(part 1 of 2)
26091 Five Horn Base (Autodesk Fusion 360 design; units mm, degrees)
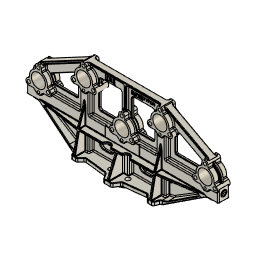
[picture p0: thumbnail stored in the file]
parameter "Bolt_Hole_Tolerance" = 0.7937 (= "( 1 / 32 ) * 1 in")
parameter "Bell_Tolerance" = 0.1984 (= "( 1 / 128 ) * 1 in")
parameter "Dowel_Hole_Tolerance" = 0.0992 (= "( 1 / 256 ) * 1 in")
sketch "Layout Profile" plane through (0, 0, 0) normal (0, 1, 0) x axis (1, 0, 0)
  line L1 (50.8, 0) -> (-50.8, 0)
  line L2 (0, -212.725) -> (0, 0)
  line L3 (263.525, -136.525) -> (-263.525, -136.525)
  line L4 (120.65, -212.725) -> (-120.65, -212.725)
  line L5 (57.5017, -12.7) -> (-57.5017, -12.7)
  circle C1 centre (120.65, -212.725) radius 80.9625
  circle C2 centre (-120.65, -212.725) radius 69.0562
  circle C3 centre (-263.525, -136.525) radius 101.6
  circle C4 centre (263.525, -136.525) radius 114.3
  arc A1 centre (0, -136.525) radius 136.525 clockwise from (57.5017, -12.7) to (-57.5017, -12.7)
  point P3 (0, 0)
  point P8 (0, -136.525)
  point P11 (0, -212.725)
  point P5 (0, -212.725)
  point P10 (120.65, -212.725)
  point P12 (120.65, -212.725)
  point P9 (-120.65, -212.725)
  point P13 (-120.65, -212.725)
  point P6 (-263.525, -136.525)
  point P14 (-263.525, -136.525)
  point P15 (0, -136.525)
  point P7 (263.525, -136.525)
  point P16 (263.525, -136.525)
  point P4 (0, 0)
  point P1 (-50.8, 0)
  point P2 (50.8, 0)
  horizontal L1
  midpoint L1 P3
  perpendicular L1 L2
  horizontal L3
  midpoint L3 P8
  coincident L2 P8
  horizontal L4
  midpoint L4 P11
  coincident P5 P11
  coincident P10 P12
  coincident P9 P13
  coincident P6 P14
  coincident P8 P15
  coincident P7 P16
  perpendicular L2 L5
  coincident L1 P4
  coincident P3 P4
  dimension "d1" distance P1 P2 = 101.6
  dimension "d2" distance L2 P6 = 263.525 (= "10 3/8")
  dimension "d3" distance L1 L3 = 136.525 (= "5 3/8")
  dimension "d4" distance P9 P10 = 241.3 (= "9 1/2")
  dimension "d5" distance L3 L4 = 76.2
  dimension "d6" diameter C1 = 161.925 (= "6 3/8")
  dimension "d7" diameter C2 = 138.1125 (= "5 7/16")
  dimension "d8" diameter C3 = 203.2
  dimension "d9" diameter A1 = 273.05 (= "10 3/4")
  dimension "d10" diameter C4 = 228.6
  dimension "d11" distance L1 L5 = 12.7 (= "( 1 / 2 ) * 1 in")
sketch "Main Profile" plane through (0, 0, 0) normal (0, 1, 0) x axis (1, 0, 0)
  line L1 (0, -171.45) -> (0, -136.525)
  line L2 (30.2459, -119.0625) -> (0, -136.525)
  line L3 (-30.2459, -119.0625) -> (0, -136.525)
  line L4 (0, -180.975) -> (0, -171.45)
  line L5 (3.175, -180.975) -> (-3.175, -180.975)
  line L6 (9.525, -165.6244) -> (9.525, -174.625)
  line L7 (35.0084, -127.3114) -> (29.9633, -130.2242)
  line L8 (30.2459, -109.5375) -> (15.0813, -109.5375)
  line L9 (0, -104.775) -> (0, -136.525)
  line L10 (0, -98.425) -> (0, -104.775)
  line L11 (3.9688, -98.425) -> (-3.9687, -98.425)
  line L12 (15.0813, -109.5375) -> (3.9688, -98.425)
  line L13 (-15.0812, -109.5375) -> (-3.9687, -98.425)
  line L14 (-30.2459, -109.5375) -> (-15.0812, -109.5375)
  line L15 (-35.0084, -127.3114) -> (-29.9633, -130.2242)
  line L16 (-9.525, -165.6244) -> (-9.525, -174.625)
  line L17 (120.65, -247.65) -> (120.65, -212.725)
  line L18 (150.8959, -195.2625) -> (120.65, -212.725)
  line L19 (90.4041, -195.2625) -> (120.65, -212.725)
  line L20 (120.65, -257.175) -> (120.65, -247.65)
  line L21 (123.825, -257.175) -> (117.475, -257.175)
  line L22 (130.175, -241.8244) -> (130.175, -250.825)
  line L23 (155.6584, -203.5114) -> (150.6133, -206.4242)
  line L24 (150.8959, -185.7375) -> (135.7312, -185.7375)
  line L25 (120.65, -180.975) -> (120.65, -212.725)
  line L26 (120.65, -174.625) -> (120.65, -180.975)
  line L27 (124.6188, -174.625) -> (116.6813, -174.625)
  line L28 (135.7312, -185.7375) -> (124.6188, -174.625)
  line L29 (111.125, -241.8244) -> (111.125, -250.825)
  line L30 (85.6416, -203.5114) -> (90.6867, -206.4242)
  line L31 (90.4041, -185.7375) -> (105.5688, -185.7375)
  line L32 (105.5688, -185.7375) -> (116.6813, -174.625)
  line L33 (0, -136.525) -> (0, 0)
  line L34 (-90.4041, -195.2625) -> (-120.65, -212.725)
  line L35 (-120.65, -257.175) -> (-120.65, -247.65)
  line L36 (-124.6187, -174.625) -> (-116.6812, -174.625)
  line L37 (-85.6416, -203.5114) -> (-90.6867, -206.4242)
  line L38 (-120.65, -174.625) -> (-120.65, -180.975)
  line L39 (-150.8959, -195.2625) -> (-120.65, -212.725)
  line L40 (-120.65, -180.975) -> (-120.65, -212.725)
  line L41 (-130.175, -241.8244) -> (-130.175, -250.825)
  line L42 (-105.5688, -185.7375) -> (-116.6812, -174.625)
  line L43 (-135.7312, -185.7375) -> (-124.6187, -174.625)
  line L44 (-120.65, -247.65) -> (-120.65, -212.725)
  line L45 (-111.125, -241.8244) -> (-111.125, -250.825)
  line L46 (-150.8959, -185.7375) -> (-135.7312, -185.7375)
  line L47 (-155.6584, -203.5114) -> (-150.6133, -206.4242)
  line L48 (-123.825, -257.175) -> (-117.475, -257.175)
  line L49 (-90.4041, -185.7375) -> (-105.5688, -185.7375)
  line L50 (263.525, -171.45) -> (263.525, -136.525)
  line L51 (293.7709, -119.0625) -> (263.525, -136.525)
  line L52 (233.2791, -119.0625) -> (263.525, -136.525)
  line L53 (263.525, -180.975) -> (263.525, -171.45)
  line L54 (266.7, -180.975) -> (260.35, -180.975)
  line L55 (273.05, -165.6244) -> (273.05, -174.625)
  line L56 (298.5334, -127.3114) -> (293.4883, -130.2242)
  line L57 (293.7709, -109.5375) -> (278.6063, -109.5375)
  line L58 (263.525, -104.775) -> (263.525, -136.525)
  line L59 (263.525, -98.425) -> (263.525, -104.775)
  line L60 (267.4938, -98.425) -> (259.5563, -98.425)
  line L61 (278.6063, -109.5375) -> (267.4938, -98.425)
  line L62 (248.4438, -109.5375) -> (259.5563, -98.425)
  line L63 (228.5166, -127.3114) -> (233.5617, -130.2242)
  line L64 (254, -165.6244) -> (254, -174.625)
  line L65 (233.2791, -109.5375) -> (248.4438, -109.5375)
  line L66 (-233.2791, -119.0625) -> (-263.525, -136.525)
  line L67 (-293.7709, -109.5375) -> (-278.6063, -109.5375)
  line L68 (-228.5166, -127.3114) -> (-233.5617, -130.2242)
  line L69 (-248.4437, -109.5375) -> (-259.5562, -98.425)
  line L70 (-293.7709, -119.0625) -> (-263.525, -136.525)
  line L71 (-263.525, -104.775) -> (-263.525, -136.525)
  line L72 (-273.05, -165.6244) -> (-273.05, -174.625)
  line L73 (-266.7, -180.975) -> (-260.35, -180.975)
  line L74 (-254, -165.6244) -> (-254, -174.625)
  line L75 (-278.6063, -109.5375) -> (-267.4937, -98.425)
  line L76 (-267.4937, -98.425) -> (-259.5562, -98.425)
  line L77 (-298.5334, -127.3114) -> (-293.4883, -130.2242)
  line L78 (-263.525, -180.975) -> (-263.525, -171.45)
  line L79 (-233.2791, -109.5375) -> (-248.4437, -109.5375)
  line L80 (-263.525, -171.45) -> (-263.525, -136.525)
  line L81 (-263.525, -98.425) -> (-263.525, -104.775)
  line L82 (263.525, -136.525) -> (-263.525, -136.525)
  line L83 (120.65, -212.725) -> (-120.65, -212.725)
  line L84 (50.8, 0) -> (-50.8, 0)
  line L85 (148.2214, -15.875) -> (-148.2214, -15.875)
  line L86 (51.5938, -3.175) -> (50.8, 0)
  line L87 (139.7, -3.175) -> (51.5938, -3.175)
  line L88 (120.65, 0) -> (120.65, -212.725)
  line L89 (-120.65, 0) -> (-120.65, -212.725)
  line L90 (263.525, 0) -> (50.8, 0)
  line L91 (263.525, -136.525) -> (263.525, 0)
  line L92 (-263.525, 0) -> (-50.8, 0)
  line L93 (-263.525, -136.525) -> (-263.525, 0)
  line L94 (0, -212.725) -> (0, -136.525)
  line L95 (269.6882, -180.2279) -> (126.8132, -256.4279)
  line L96 (256.8125, -179.8984) -> (130.175, -247.4383)
  line L97 (237.8236, -161.2391) -> (169.4422, -197.7091)
  line L98 (303.2959, -79.375) -> (303.2959, -119.0625)
  line L99 (3.175, -79.375) -> (303.2959, -79.375)
  line L100 (223.8873, -117.475) -> (134.9375, -117.475)
  line L101 (157.1625, -136.525) -> (228.7446, -136.525)
  line L102 (123.825, -15.875) -> (123.825, -174.625)
  line L103 (117.475, -15.875) -> (117.475, -174.625)
  line L104 (263.525, -79.375) -> (139.7, -3.175)
  line L105 (251.4089, -79.375) -> (148.2214, -15.875)
  line L106 (263.525, -85.725) -> (263.525, -79.375)
  line L107 (3.175, -85.725) -> (263.525, -85.725)
  line L108 (3.175, -98.425) -> (3.175, -85.725)
  line L109 (3.175, -15.875) -> (3.175, -79.375)
  line L110 (3.175, -79.375) -> (3.175, -85.725)
  line L111 (134.9375, -79.375) -> (134.9375, -184.9438)
  line L112 (106.3625, -79.375) -> (106.3625, -184.9438)
  line L113 (134.9375, -15.875) -> (134.9375, -79.375)
  line L114 (106.3625, -15.875) -> (106.3625, -79.375)
  line L115 (153.9875, -182.5003) -> (153.9875, -139.7)
  line L116 (-117.475, -257.175) -> (117.475, -257.175)
  line L117 (0, -257.175) -> (0, -212.725)
  line L118 (3.175, -250.825) -> (111.125, -250.825)
  line L119 (3.175, -180.975) -> (3.175, -250.825)
  line L120 (80.9625, -225.425) -> (22.225, -225.425)
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  point P4 (0, -136.525)
  point P7 (0, -136.525)
  point P8 (0, -136.525)
  point P9 (0, -171.45)
  point P10 (0, -171.45)
  point P17 (0, -171.45)
  point P21 (0, -180.975)
  point P18 (0, -180.975)
  point P35 (0, -136.525)
  point P36 (0, -104.775)
  point P37 (0, -104.775)
  point P38 (0, -104.775)
  point P42 (0, -98.425)
  point P39 (0, -98.425)
  point P20 (3.175, -180.975)
  point P57 (-3.175, -180.975)
  point P22 (9.525, -174.625)
  point P55 (-9.525, -174.625)
  point P24 (9.525, -165.6244)
  point P54 (-9.525, -165.6244)
  point P25 (11.43, -162.7144)
  point P52 (-11.43, -162.7144)
  point P27 (28.3957, -133.329)
  point P50 (-28.3957, -133.329)
  point P29 (29.9633, -130.2242)
  point P48 (-29.9633, -130.2242)
  point P31 (35.0084, -127.3114)
  point P47 (-35.0084, -127.3114)
  point P32 (15.0813, -109.5375)
  point P44 (-15.0812, -109.5375)
  point P33 (30.2459, -109.5375)
  point P45 (-30.2459, -109.5375)
  point P41 (3.9688, -98.425)
  point P43 (-3.9687, -98.425)
  point P5 (120.65, -212.725)
  point P58 (120.65, -212.725)
  point P59 (120.65, -212.725)
  point P60 (120.65, -247.65)
  point P61 (120.65, -247.65)
  point P68 (120.65, -247.65)
  point P72 (120.65, -257.175)
  point P69 (120.65, -257.175)
  point P86 (120.65, -212.725)
  point P87 (120.65, -180.975)
  point P88 (120.65, -180.975)
  point P89 (120.65, -180.975)
  point P93 (120.65, -174.625)
  point P90 (120.65, -174.625)
  point P71 (123.825, -257.175)
  point P95 (117.475, -257.175)
  point P73 (130.175, -250.825)
  point P96 (111.125, -250.825)
  point P75 (130.175, -241.8244)
  point P97 (111.125, -241.8244)
  point P76 (132.08, -238.9144)
  point P99 (109.22, -238.9144)
  point P78 (149.0457, -209.529)
  point P101 (92.2543, -209.529)
  point P80 (150.6133, -206.4242)
  point P103 (90.6867, -206.4242)
  point P82 (155.6584, -203.5114)
  point P104 (85.6416, -203.5114)
  point P83 (135.7312, -185.7375)
  point P107 (105.5688, -185.7375)
  point P84 (150.8959, -185.7375)
  point P106 (90.4041, -185.7375)
  point P92 (124.6188, -174.625)
  point P108 (116.6813, -174.625)
  point P1 (0, 0)
  point P109 (0, 0)
  point P28 (0, -136.525)
  point P110 (0, -136.525)
  point P156 (-120.65, -212.725)
  point P151 (-120.65, -212.725)
  point P141 (-120.65, -247.65)
  point P63 (120.65, -212.725)
  point P147 (-120.65, -212.725)
  point P64 (150.8959, -195.2625)
  point P139 (-150.8959, -195.2625)
  point P66 (120.65, -212.725)
  point P137 (-120.65, -212.725)
  point P67 (90.4041, -195.2625)
  point P158 (-90.4041, -195.2625)
  point P144 (-120.65, -247.65)
  point P114 (-120.65, -257.175)
  point P70 (117.475, -257.175)
  point P140 (-117.475, -257.175)
  point P120 (-123.825, -257.175)
  point P123 (-120.65, -257.175)
  point P115 (-130.175, -250.825)
  point P118 (-130.175, -241.8244)
  point P138 (-132.08, -238.9144)
  point P155 (-149.0457, -209.529)
  point P159 (-150.6133, -206.4242)
  point P161 (-155.6584, -203.5114)
  point P136 (-135.7312, -185.7375)
  point P134 (-150.8959, -185.7375)
  point P112 (-120.65, -212.725)
  point P133 (-120.65, -180.975)
  point P111 (-120.65, -180.975)
  point P121 (-120.65, -174.625)
  point P91 (116.6813, -174.625)
  point P162 (-116.6812, -174.625)
  point P116 (-124.6187, -174.625)
  point P119 (-120.65, -174.625)
  point P153 (-117.475, -257.175)
  point P117 (-111.125, -250.825)
  point P150 (-111.125, -241.8244)
  point P145 (-109.22, -238.9144)
  point P152 (-92.2543, -209.529)
  point P129 (-90.6867, -206.4242)
  point P130 (-85.6416, -203.5114)
  point P146 (-90.4041, -185.7375)
  point P131 (-105.5688, -185.7375)
  point P124 (-116.6812, -174.625)
  point P6 (263.525, -136.525)
  point P163 (263.525, -136.525)
  point P164 (263.525, -136.525)
  point P165 (263.525, -171.45)
  point P166 (263.525, -171.45)
  point P173 (263.525, -171.45)
  point P177 (263.525, -180.975)
  point P174 (263.525, -180.975)
  point P191 (263.525, -104.775)
  point P192 (263.525, -104.775)
  point P193 (263.525, -104.775)
  point P197 (263.525, -98.425)
  point P194 (263.525, -98.425)
  point P176 (266.7, -180.975)
  point P212 (260.35, -180.975)
  point P178 (273.05, -174.625)
  point P210 (254, -174.625)
  point P180 (273.05, -165.6244)
  point P209 (254, -165.6244)
  point P181 (274.955, -162.7144)
  point P207 (252.095, -162.7144)
  point P183 (291.9207, -133.329)
  point P205 (235.1293, -133.329)
  point P185 (293.4883, -130.2242)
  point P203 (233.5617, -130.2242)
  point P187 (298.5334, -127.3114)
  point P201 (228.5166, -127.3114)
  point P188 (278.6063, -109.5375)
  point P199 (248.4438, -109.5375)
  point P189 (293.7709, -109.5375)
  point P202 (233.2791, -109.5375)
  point P196 (267.4938, -98.425)
  point P198 (259.5563, -98.425)
  point P213 (248.4438, -109.5375)
  point P214 (233.2791, -109.5375)
  point P236 (-263.525, -136.525)
  point P215 (-263.525, -136.525)
  point P217 (-263.525, -171.45)
  point P167 (263.525, -136.525)
  point P230 (-263.525, -136.525)
  point P168 (293.7709, -119.0625)
  point P229 (-293.7709, -119.0625)
  point P170 (263.525, -136.525)
  point P218 (-263.525, -136.525)
  point P171 (233.2791, -119.0625)
  point P223 (-233.2791, -119.0625)
  point P227 (-263.525, -171.45)
  point P262 (-263.525, -180.975)
  point P175 (260.35, -180.975)
  point P238 (-260.35, -180.975)
  point P264 (-266.7, -180.975)
  point P231 (-263.525, -180.975)
  point P254 (-273.05, -174.625)
  point P248 (-273.05, -165.6244)
  point P265 (-274.955, -162.7144)
  point P255 (-291.9207, -133.329)
  point P267 (-293.4883, -130.2242)
  point P260 (-298.5334, -127.3114)
  point P257 (-278.6063, -109.5375)
  point P266 (-293.7709, -109.5375)
  point P224 (-263.525, -104.775)
  point P226 (-263.525, -104.775)
  point P225 (-263.525, -98.425)
  point P195 (259.5563, -98.425)
  point P239 (-259.5562, -98.425)
  point P222 (-267.4937, -98.425)
  point P251 (-263.525, -98.425)
  point P244 (-259.5562, -98.425)
  point P234 (-248.4437, -109.5375)
  point P220 (-228.5166, -127.3114)
  point P250 (-233.2791, -109.5375)
  point P235 (-233.5617, -130.2242)
  point P233 (-235.1293, -133.329)
  point P232 (-252.095, -162.7144)
  point P219 (-254, -165.6244)
  point P216 (-254, -174.625)
  point P256 (-260.35, -180.975)
  point P249 (-248.4437, -109.5375)
  point P237 (-233.2791, -109.5375)
  point P268 (263.525, -136.525)
  point P3 (-120.65, -212.725)
  point P269 (-120.65, -212.725)
  point P272 (0, 0)
  point P275 (0, -15.875)
  point P278 (120.65, -212.725)
  point P206 (263.525, -136.525)
  point P282 (263.525, -136.525)
  point P279 (120.65, 0)
  point P263 (-263.525, -136.525)
  point P284 (-263.525, -136.525)
  point P280 (-120.65, 0)
  point P285 (0, -212.725)
  point P288 (130.175, -247.4383)
  point P301 (228.7446, -136.525)
  point P303 (157.1625, -136.525)
  point P308 (263.525, -79.375)
  point P309 (251.4089, -79.375)
  point P310 (263.525, -85.725)
  point P313 (3.175, -15.875)
  point P305 (123.825, -15.875)
  point P307 (117.475, -15.875)
  point P314 (134.9375, -184.9438)
  point P316 (106.3625, -184.9438)
  point P315 (134.9375, -79.375)
  point P317 (106.3625, -79.375)
  point P318 (134.9375, -15.875)
  point P319 (106.3625, -15.875)
  point P304 (123.825, -174.625)
  point P306 (117.475, -174.625)
  point P299 (134.9375, -117.475)
  point P312 (3.175, -98.425)
  point P327 (0, -257.175)
  point P330 (3.175, -180.975)
  point P344 (34.7804, -136.525)
  point P346 (80.9625, -136.525)
  point P352 (273.05, -172.446)
  point P357 (3.175, -247.65)
  point P356 (6.35, -250.825)
  point P271 (50.8, 0)
  point P373 (-50.8, 0)
  point P274 (148.2214, -15.875)
  point P377 (-148.2214, -15.875)
  point P276 (51.5938, -3.175)
  point P374 (-51.5937, -3.175)
  point P277 (139.7, -3.175)
  point P375 (-139.7, -3.175)
  point P290 (169.4422, -197.7091)
  point P386 (-169.4422, -197.7091)
  point P291 (237.8236, -161.2391)
  point P387 (-237.8236, -161.2391)
  point P292 (238.8018, -156.4455)
  point P389 (-238.8018, -156.4455)
  point P294 (231.9065, -139.4114)
  point P391 (-231.9065, -139.4114)
  point P296 (303.2959, -119.0625)
  point P379 (-303.2959, -119.0625)
  point P297 (303.2959, -79.375)
  point P361 (-303.2959, -79.375)
  point P298 (3.175, -79.375)
  point P362 (-3.175, -79.375)
  point P380 (-134.9375, -117.475)
  point P300 (223.8873, -117.475)
  point P382 (-223.8873, -117.475)
  point P393 (-228.7446, -136.525)
  point P398 (-157.1625, -136.525)
  point P363 (-123.825, -174.625)
  point P364 (-123.825, -15.875)
  point P365 (-117.475, -174.625)
  point P366 (-117.475, -15.875)
  point P376 (-263.525, -79.375)
  point P378 (-251.4089, -79.375)
  point P359 (-263.525, -85.725)
  point P311 (3.175, -85.725)
  point P360 (-3.175, -85.725)
  point P371 (-134.9375, -184.9438)
  point P369 (-134.9375, -79.375)
  point P372 (-106.3625, -184.9438)
  point P367 (-106.3625, -79.375)
  point P370 (-134.9375, -15.875)
  point P368 (-106.3625, -15.875)
  point P320 (153.9875, -139.7)
  point P396 (-153.9875, -139.7)
  point P322 (153.9875, -182.5003)
  point P395 (-153.9875, -182.5003)
  point P323 (156.5609, -187.6052)
  point P384 (-156.5609, -187.6052)
  point P325 (160.2308, -193.3687)
  point P383 (-160.2308, -193.3687)
  point P328 (111.125, -250.825)
  point P414 (-111.125, -250.825)
  point P329 (3.175, -250.825)
  point P415 (-3.175, -250.825)
  point P419 (-3.175, -180.975)
  point P331 (22.225, -225.425)
  point P409 (-22.225, -225.425)
  point P332 (80.9625, -225.425)
  point P410 (-80.9625, -225.425)
  point P333 (15.875, -219.075)
  point P407 (-15.875, -219.075)
  point P335 (15.875, -165.7971)
  point P406 (-15.875, -165.7971)
  point P337 (87.3125, -184.2162)
  point P411 (-87.3125, -184.2162)
  point P339 (87.3125, -142.875)
  point P413 (-87.3125, -142.875)
  point P340 (17.3182, -163.136)
  point P404 (-17.3182, -163.136)
  point P342 (31.6185, -139.4114)
  point P402 (-31.6185, -139.4114)
  point P399 (-34.7804, -136.525)
  point P400 (-80.9625, -136.525)
  point P348 (39.6377, -117.475)
  point P381 (-39.6377, -117.475)
  point P418 (-6.35, -250.825)
  point P417 (-3.175, -247.65)
  point P286 (126.8132, -256.4279)
  point P420 (-126.8132, -256.4279)
  point P287 (269.6882, -180.2279)
  point P421 (-269.6882, -180.2279)
  point P422 (-130.175, -247.4383)
  point P289 (256.8125, -179.8984)
  point P423 (-256.8125, -179.8984)
  point P424 (62.7063, -79.375)
  point P425 (62.7063, -15.875)
  point P426 (-3.175, -79.375)
  point P428 (-3.175, -85.725)
  point P429 (-3.175, -98.425)
  point P427 (-3.175, -15.875)
  point P431 (106.3625, -47.625)
  point P448 (-62.7063, -79.375)
  point P449 (-62.7063, -15.875)
  point P430 (19.05, -47.625)
  point P446 (-19.05, -47.625)
  point P447 (-106.3625, -47.625)
  point P432 (53.1813, -60.325)
  point P443 (-53.1813, -60.325)
  point P433 (72.2313, -60.325)
  point P441 (-72.2313, -60.325)
  point P434 (53.1813, -34.925)
  point P445 (-53.1813, -34.925)
  point P435 (72.2313, -34.925)
  point P442 (-72.2313, -34.925)
  point P450 (134.9375, -54.3904)
  point P454 (173.5531, -79.375)
  point P461 (-134.9375, -54.3904)
  point P451 (139.7765, -51.6864)
  point P459 (-139.7765, -51.6864)
  point P453 (175.2172, -73.496)
  point P458 (-175.2172, -73.496)
  point P457 (-173.5531, -79.375)
  point P462 (19.05, -79.375)
  point P463 (19.05, -15.875)
  point P465 (-19.05, -15.875)
  point P466 (0, 0)
  point P468 (0, -79.375)
  point P475 (-80.9625, -225.425)
  point P336 (85.7041, -186.9778)
  point P482 (-85.7041, -186.9778)
  point P480 (-87.3125, -184.2162)
  point P469 (87.3125, -219.075)
  point P476 (-87.3125, -219.075)
  point P471 (87.3125, -208.0247)
  point P477 (-87.3125, -208.0247)
  point P472 (84.7391, -202.9198)
  point P479 (-84.7391, -202.9198)
  point P12 (0, -136.525)
  point P40 (-3.9687, -98.425)
  point P15 (0, -136.525)
  point P184 (263.525, -136.525)
  point P270 (-50.8, 0)
  point P438 (40.4813, -47.625)
  point P439 (84.9313, -47.625)
  coincident P4 P7
  coincident P4 P8
  vertical L1
  coincident P9 P10
  coincident P10 P17
  vertical L4
  horizontal L5
  midpoint L5 P21
  coincident P18 P21
  vertical L6
  horizontal L8
  coincident P4 P35
  vertical L9
  coincident P36 P37
  coincident P37 P38
  parallel L9 L10
  horizontal L11
  midpoint L11 P42
  coincident P39 P42
  symmetric L1 P20 P57
  symmetric L1 P22 P55
  symmetric L1 P24 P54
  symmetric L1 P25 P52
  symmetric L1 P27 P50
  symmetric L1 P29 P48
  symmetric L1 P31 P47
  symmetric L1 P32 P44
  symmetric L1 P33 P45
  symmetric L1 P41 P43
  coincident P5 P58
  coincident P58 P59
  vertical L17
  coincident P60 P61
  coincident P61 P68
  parallel L17 L20
  horizontal L21
  midpoint L21 P72
  coincident P69 P72
  vertical L22
  horizontal L24
  coincident P5 P86
  vertical L25
  coincident P87 P88
  coincident P88 P89
  parallel L25 L26
  horizontal L27
  midpoint L27 P93
  coincident P90 P93
  symmetric L17 P71 P95
  symmetric L17 P73 P96
  symmetric L17 P75 P97
  symmetric L17 P76 P99
  symmetric L17 P78 P101
  symmetric L17 P80 P103
  symmetric L17 P82 P104
  symmetric L17 P83 P107
  symmetric L17 P84 P106
  symmetric L17 P92 P108
  coincident P1 P109
  coincident P28 P110
  symmetric P5 L33 P156
  symmetric P59 L33 P151
  symmetric P60 L33 P141
  symmetric P63 L33 P147
  symmetric P64 L33 P139
  symmetric P66 L33 P137
  symmetric P67 L33 P158
  symmetric P68 L33 P144
  symmetric P69 L33 P114
  symmetric P70 L33 P140
  symmetric P71 L33 P120
  symmetric P72 L33 P123
  symmetric P73 L33 P115
  symmetric P75 L33 P118
  symmetric P76 L33 P138
  symmetric P78 L33 P155
  symmetric P80 L33 P159
  symmetric P82 L33 P161
  symmetric P83 L33 P136
  symmetric P84 L33 P134
  symmetric P86 L33 P112
  symmetric P87 L33 P133
  symmetric P89 L33 P111
  symmetric P90 L33 P121
  symmetric P91 L33 P162
  symmetric P92 L33 P116
  symmetric P93 L33 P119
  symmetric P95 L33 P153
  symmetric P96 L33 P117
  symmetric P97 L33 P150
  symmetric P99 L33 P145
  symmetric P101 L33 P152
  symmetric P103 L33 P129
  symmetric P104 L33 P130
  symmetric P106 L33 P146
  symmetric P107 L33 P131
  symmetric P108 L33 P124
  coincident P6 P163
  coincident P163 P164
  vertical L50
  coincident P165 P166
  coincident P166 P173
  vertical L53
  horizontal L54
  midpoint L54 P177
  coincident P174 P177
  vertical L55
  horizontal L57
  parallel L50 L58
  coincident P191 P192
  coincident P192 P193
  parallel L58 L59
  horizontal L60
  midpoint L60 P197
  coincident P194 P197
  symmetric L50 P176 P212
  symmetric L50 P178 P210
  symmetric L50 P180 P209
  symmetric L50 P181 P207
  symmetric L50 P183 P205
  symmetric L50 P185 P203
  symmetric L50 P187 P201
  symmetric L50 P188 P199
  symmetric L50 P189 P202
  symmetric L50 P196 P198
  symmetric L50 P188 P213
  symmetric L50 P189 P214
  symmetric P6 L33 P236
  symmetric L33 P164 P215
  symmetric L33 P165 P217
  symmetric L33 P167 P230
  symmetric L33 P168 P229
  symmetric L33 P170 P218
  symmetric L33 P171 P223
  symmetric L33 P173 P227
  symmetric L33 P174 P262
  symmetric L33 P175 P238
  symmetric L33 P176 P264
  symmetric L33 P177 P231
  symmetric L33 P178 P254
  symmetric L33 P180 P248
  symmetric L33 P181 P265
  symmetric L33 P183 P255
  symmetric L33 P185 P267
  symmetric L33 P187 P260
  symmetric L33 P188 P257
  symmetric L33 P189 P266
  symmetric L33 P191 P224
  symmetric L33 P193 P226
  symmetric L33 P194 P225
  symmetric L33 P195 P239
  symmetric L33 P196 P222
  symmetric L33 P197 P251
  symmetric L33 P198 P244
  symmetric L33 P199 P234
  symmetric L33 P201 P220
  symmetric L33 P202 P250
  symmetric L33 P203 P235
  symmetric L33 P205 P233
  symmetric L33 P207 P232
  symmetric L33 P209 P219
  symmetric L33 P210 P216
  symmetric L33 P212 P256
  symmetric L33 P213 P249
  symmetric L33 P214 P237
  coincident P6 P268
  coincident P3 P269
  horizontal L84
  midpoint L84 P272
  coincident P1 P272
  horizontal L85
  midpoint L85 P275
  coincident L33 P275
  parallel L84 L87
  coincident P5 P278
  parallel L25 L88
  parallel L40 L89
  perpendicular L88 L90
  coincident P206 P282
  vertical L91
  coincident P279 L90
  parallel L84 L92
  coincident P263 P284
  vertical L93
  coincident P280 L92
  midpoint L83 P285
  parallel L95 L96
  coincident L22 P288
  parallel L96 L97
  vertical L98
  perpendicular L98 L99
  horizontal L100
  coincident L82 P301
  coincident L82 P303
  parallel L82 L101
  vertical L102
  vertical L103
  symmetric L88 L102 L103
  coincident L91 P308
  coincident L99 P308
  parallel L104 L105
  coincident L99 P309
  coincident L91 P310
  perpendicular L106 L107
  vertical L108
  coincident L85 P313
  perpendicular L85 L109
  vertical L110
  coincident L85 P305
  coincident L85 P307
  coincident L28 P314
  vertical L111
  coincident L32 P316
  parallel L103 L112
  coincident L99 P315
  coincident L99 P317
  coincident L85 P318
  perpendicular L85 L113
  coincident L85 P319
  perpendicular L85 L114
  coincident L27 P304
  coincident L27 P306
  vertical L115
  coincident P299 L111
  coincident L11 P312
  midpoint L116 P327
  perpendicular L29 L118
  coincident L5 P330
  vertical L119
  parallel L83 L120
  coincident L82 P344
  coincident L82 P346
  coincident L55 P352
  coincident L119 P357
  coincident L118 P356
  symmetric P271 L117 P373
  symmetric P274 L117 P377
  symmetric P276 L117 P374
  symmetric P277 L117 P375
  symmetric P290 L117 P386
  symmetric P291 L117 P387
  symmetric P292 L117 P389
  symmetric P294 L117 P391
  symmetric P296 L117 P379
  symmetric P297 L117 P361
  symmetric P298 L117 P362
  symmetric P299 L117 P380
  symmetric P300 L117 P382
  symmetric P301 L117 P393
  symmetric P303 L117 P398
  symmetric P304 L117 P363
  symmetric P305 L117 P364
  symmetric P306 L117 P365
  symmetric P307 L117 P366
  symmetric P308 L117 P376
  symmetric P309 L117 P378
  symmetric P310 L117 P359
  symmetric P311 L117 P360
  symmetric P314 L117 P371
  symmetric P315 L117 P369
  symmetric P316 L117 P372
  symmetric P317 L117 P367
  symmetric P318 L117 P370
  symmetric P319 L117 P368
  symmetric P320 L117 P396
  symmetric P322 L117 P395
  symmetric P323 L117 P384
  symmetric P325 L117 P383
  symmetric L117 P328 P414
  symmetric L117 P329 P415
  symmetric L117 P330 P419
  symmetric L117 P331 P409
  symmetric L117 P332 P410
  symmetric L117 P333 P407
  symmetric L117 P335 P406
  symmetric L117 P337 P411
  symmetric L117 P339 P413
  symmetric L117 P340 P404
  symmetric L117 P342 P402
  symmetric L117 P344 P399
  symmetric L117 P346 P400
  symmetric L117 P348 P381
  symmetric L117 P356 P418
  symmetric L117 P357 P417
  symmetric P286 L117 P420
  symmetric P287 L117 P421
  symmetric P288 L117 P422
  symmetric P289 L117 P423
  coincident L99 P424
  coincident L85 P425
  symmetric L94 P298 P426
  symmetric L94 P311 P428
  symmetric L94 P312 P429
  symmetric L94 P313 P427
  coincident L114 P431
  midpoint L114 P431
  symmetric L94 P424 P448
  symmetric L94 P425 P449
  symmetric L94 P430 P446
  symmetric L94 P431 P447
  symmetric L94 P432 P443
  symmetric L94 P433 P441
  symmetric L94 P434 P445
  symmetric L94 P435 P442
  coincident L113 P450
  coincident L99 P454
  symmetric L117 P450 P461
  symmetric L117 P451 P459
  symmetric L117 P453 P458
  symmetric L117 P454 P457
  coincident L99 P462
  coincident L85 P463
  coincident L85 P465
  coincident P272 P466
  coincident L33 P468
  symmetric L117 P332 P475
  symmetric L117 P336 P482
  symmetric L117 P337 P480
  symmetric L117 P469 P476
  symmetric L117 P471 P477
  symmetric L117 P472 P479
  dimension "d14" diameter = 44.6484 (= "1 3/4  + Bell_Tolerance")
  dimension "d15" distance P8 P9 = 34.925 (= "1 3/8")
  dimension "d16" diameter = 10.3188 (= "( 3 / 8 ) * 1 in + Bolt_Hole_Tolerance")
  dimension "d19" distance P12 L5 = 44.45 (= "1 3/4")
  dimension "d20" radius = 6.35 (= "( 1 / 4 ) * 1 in")
  dimension "d21" distance P10 L6 = 9.525 (= "( 3 / 8 ) * 1 in")
  dimension "d22" radius = 28.575 (= "1 1/8")
  dimension "d23" radius = 3.175 (= "( 1 / 8 ) * 1 in")
  dimension "d24" radius = 3.175 (= "( 1 / 8 ) * 1 in")
  dimension "d25" angle L7 L8 = 30
  dimension "d26" radius = 9.525 (= "( 3 / 8 ) * 1 in")
  dimension "d27" diameter = 7.9375 (= "( 5 / 16 ) * 1 in")
  dimension "d28" distance P35 P36 = 31.75 (= "1 1/4")
  dimension "d29" angle L8 L12 = 135
  dimension "d30" distance P40 P41 = 7.9375 (= "( 5 / 16 ) * 1 in")
  dimension "d31" distance P15 L11 = 38.1 (= "1 1/2")
  dimension "d32" diameter = 44.6484 (= "1 3/4  + Bell_Tolerance")
  dimension "d33" diameter = 10.3188 (= "( 3 / 8 ) * 1 in + Bolt_Hole_Tolerance")
  dimension "d34" distance P59 P60 = 34.925 (= "1 3/8")
  dimension "d37" distance P66 L21 = 44.45 (= "1 3/4")
  dimension "d38" radius = 6.35 (= "( 1 / 4 ) * 1 in")
  dimension "d39" distance P61 L22 = 9.525 (= "( 3 / 8 ) * 1 in")
  dimension "d40" radius = 3.175 (= "( 1 / 8 ) * 1 in")
  dimension "d41" radius = 28.575 (= "1 1/8")
  dimension "d42" radius = 3.175 (= "( 1 / 8 ) * 1 in")
  dimension "d43" radius = 9.525 (= "( 3 / 8 ) * 1 in")
  dimension "d44" angle L23 L24 = 30
  dimension "d45" diameter = 7.9375 (= "( 5 / 16 ) * 1 in")
  dimension "d46" angle L24 L28 = 135
  dimension "d47" distance P91 P92 = 7.9375 (= "( 5 / 16 ) * 1 in")
  dimension "d48" distance P66 L27 = 38.1 (= "1 1/2")
  dimension "d49" distance P63 P88 = 31.75 (= "1 1/4")
  dimension "d50" diameter = 44.6484 (= "1 3/4  + Bell_Tolerance")
  dimension "d51" diameter = 10.3188 (= "( 3 / 8 ) * 1 in + Bolt_Hole_Tolerance")
  dimension "d52" distance P164 P165 = 34.925 (= "1 3/8")
  dimension "d55" distance P167 L54 = 44.45 (= "1 3/4")
  dimension "d56" radius = 6.35 (= "( 1 / 4 ) * 1 in")
  dimension "d57" distance L50 L55 = 9.525 (= "( 3 / 8 ) * 1 in")
  dimension "d58" radius = 3.175 (= "( 1 / 8 ) * 1 in")
  dimension "d59" radius = 28.575 (= "1 1/8")
  dimension "d60" radius = 3.175 (= "( 1 / 8 ) * 1 in")
  dimension "d61" radius = 9.525 (= "( 3 / 8 ) * 1 in")
  dimension "d62" angle L56 L57 = 30
  dimension "d63" diameter = 7.9375 (= "( 5 / 16 ) * 1 in")
  dimension "d64" angle L57 L61 = 135
  dimension "d65" distance P195 P196 = 7.9375 (= "( 5 / 16 ) * 1 in")
  dimension "d66" distance P184 P192 = 31.75 (= "1 1/4")
  dimension "d67" distance P184 L60 = 38.1 (= "1 1/2")
  dimension "d68" distance P270 P271 = 101.6
  dimension "d71" distance L87 L90 = 3.175 (= "( 1 / 8 ) * 1 in")
  dimension "d72" distance L84 L85 = 15.875 (= "( 5 / 8 ) * 1 in")
  dimension "d75" distance L95 L96 = 6.35 (= "( 1 / 4 ) * 1 in")
  dimension "d79" distance = 3.175 (= "( 1 / 8 ) * 1 in")
  dimension "d80" radius = 3.175 (= "( 1 / 8 ) * 1 in")
  dimension "d81" distance L82 L100 = 19.05 (= "( 3 / 4 ) * 1 in")
  dimension "d82" distance L99 L100 = 38.1 (= "1 1/2")
  dimension "d83" radius = 3.175 (= "( 1 / 8 ) * 1 in")
  dimension "d84" distance L102 L103 = 6.35 (= "( 1 / 4 ) * 1 in")
  dimension "d85" distance L33 P277 = 139.7 (= "5 1/2")
  dimension "d86" distance L104 L105 = 6.35 (= "( 1 / 4 ) * 1 in")
  dimension "d87" distance L95 L97 = 31.75
  dimension "d88" distance L99 L107 = 6.35 (= "( 1 / 4 ) * 1 in")
  dimension "d89" distance L33 L109 = 3.175 (= "( 1 / 8 ) * 1 in")
  dimension "d90" distance L111 L112 = 28.575 (= "1 1/8")
  dimension "d91" radius = 3.175 (= "( 1 / 8 ) * 1 in")
  dimension "d92" distance L111 L115 = 19.05 (= "( 3 / 4 ) * 1 in")
  dimension "d93" radius = 6.35 (= "( 1 / 4 ) * 1 in")
  dimension "d94" radius = 6.35 (= "( 1 / 4 ) * 1 in")
  dimension "d96" distance L116 L118 = 6.35 (= "( 1 / 4 ) * 1 in")
  dimension "d97" distance L117 L119 = 3.175 (= "( 1 / 8 ) * 1 in")
  dimension "d98" radius = 6.35 (= "( 1 / 4 ) * 1 in")
  dimension "d99" distance = 12.7 (= "( 1 / 2 ) * 1 in")
  dimension "d100" distance L116 L120 = 31.75 (= "1 1/4")
  dimension "d104" radius = 3.175 (= "( 1 / 8 ) * 1 in")
  dimension "d105" distance = 3.175 (= "( 1 / 8 ) * 1 in")
  dimension "d106" radius = 3.175 (= "( 1 / 8 ) * 1 in")
  dimension "d107" radius = 3.175 (= "( 1 / 8 ) * 1 in")
  dimension "d108" radius = 6.35 (= "( 1 / 4 ) * 1 in")
  dimension "d109" distance = 19.05 (= "( 3 / 4 ) * 1 in")
  dimension "d110" radius = 3.175 (= "( 1 / 8 ) * 1 in")
  dimension "d112" distance = 6.35 (= "( 1 / 4 ) * 1 in")
  dimension "d113" radius = 3.175 (= "( 1 / 8 ) * 1 in")
  dimension "d114" radius = 3.175 (= "( 1 / 8 ) * 1 in")
  dimension "d115" distance = 43.6562
  dimension "d116" distance P438 P439 = 44.45 (= "1 3/4")
  dimension "d117" distance = 25.4
  dimension "d118" radius = 3.175 (= "( 1 / 8 ) * 1 in")
  dimension "d119" radius = 3.175 (= "( 1 / 8 ) * 1 in")
  dimension "d120" distance = 34.925 (= "1 3/8")
  dimension "d130" distance = 38.1 (= "1 1/2")
  dimension "d203" distance P271 P276 = 0.7937 (= "( 1 / 32 ) * 1 in")
  dimension "d481" radius = 6.35 (= "( 1 / 4 ) * 1 in")
  dimension "d482" radius = 6.35 (= "( 1 / 4 ) * 1 in")
  dimension "d18" C-Pattern1-Angle = 360
  dimension "d36" C-Pattern2-Angle = 360
  dimension "d54" C-Pattern3-Angle = 360
work_plane "WorkPlane1" RotateAngle 0
extrude "Extrude1" new body sketch "Main Profile" distance 20.6375 (= "( 13 / 16 ) * 1 in")
extrude "Extrude2" add sketch "Main Profile" distance 39.6875 (= "1 9/16")
extrude "Extrude3" add sketch "Main Profile" distance 34.925 (= "1 3/8")
extrude "Extrude4" add sketch "Main Profile" distance 7.9375 (= "( 5 / 16 ) * 1 in")
extrude "Extrude5" add sketch "Main Profile" distance 130.175 (= "5 1/8")
revolve "Revolve1" sketch "Main Profile" AlongAngle 360
sketch "Bottom Profile" plane through (0, 0, 0) normal (0, 0, -1) x axis (1, 0, 0)
  line L1 (0, 38.1) -> (0, 0)
  line L2 (26.9408, 26.9408) -> (0, 0)
  line L3 (0, 65.0875) -> (0, 38.1)
  line L4 (12.7, 65.0875) -> (-12.7, 65.0875)
  line L5 (25.4, 44.9083) -> (12.7, 65.0875)
  line L6 (98.425, 36.4916) -> (25.4, 44.9083)
  line L7 (120.65, 0) -> (0, 0)
  line L8 (120.65, 50.8) -> (120.65, 0)
  line L9 (129.3812, 50.8) -> (111.9187, 50.8)
  line L10 (98.425, 36.4916) -> (111.9187, 50.8)
  line L11 (136.525, 32.1003) -> (129.3812, 50.8)
  line L12 (263.525, 17.4625) -> (136.525, 32.1003)
  line L13 (263.525, 17.4625) -> (263.525, 65.0875)
  line L14 (98.425, 36.4916) -> (136.525, 32.1003)
  line L15 (263.525, 65.0875) -> (139.7, 65.0875)
  line L16 (139.7, 65.0875) -> (-139.7, 65.0875)
  line L17 (25.4, -44.9083) -> (12.7, -65.0875)
  line L18 (98.425, -36.4916) -> (25.4, -44.9083)
  line L19 (129.3812, -50.8) -> (111.9187, -50.8)
  line L20 (98.425, -36.4916) -> (111.9187, -50.8)
  line L21 (136.525, -32.1003) -> (129.3812, -50.8)
  line L22 (120.65, -50.8) -> (120.65, 0)
  line L23 (98.425, -36.4916) -> (136.525, -32.1003)
  line L24 (263.525, -17.4625) -> (136.525, -32.1003)
  line L25 (263.525, -65.0875) -> (139.7, -65.0875)
  line L26 (139.7, -65.0875) -> (-139.7, -65.0875)
  line L27 (263.525, -17.4625) -> (263.525, -65.0875)
  line L28 (-25.4, 44.9083) -> (-12.7, 65.0875)
  line L29 (-98.425, 36.4916) -> (-25.4, 44.9083)
  line L30 (-98.425, 36.4916) -> (-111.9187, 50.8)
  line L31 (-129.3812, 50.8) -> (-111.9187, 50.8)
  line L32 (-136.525, 32.1003) -> (-129.3812, 50.8)
  line L33 (-263.525, 17.4625) -> (-136.525, 32.1003)
  line L34 (-98.425, 36.4916) -> (-136.525, 32.1003)
  line L35 (-98.425, -36.4916) -> (-136.525, -32.1003)
  line L36 (-98.425, -36.4916) -> (-25.4, -44.9083)
  line L37 (-25.4, -44.9083) -> (-12.7, -65.0875)
  line L38 (-98.425, -36.4916) -> (-111.9187, -50.8)
  line L39 (-129.3812, -50.8) -> (-111.9187, -50.8)
  line L40 (-136.525, -32.1003) -> (-129.3812, -50.8)
  line L41 (-263.525, -17.4625) -> (-136.525, -32.1003)
  line L42 (-263.525, 65.0875) -> (-139.7, 65.0875)
  line L43 (-263.525, 17.4625) -> (-263.525, 65.0875)
  line L44 (-139.7, 65.0875) -> (139.7, 65.0875)
  line L45 (-263.525, -17.4625) -> (-263.525, -65.0875)
  line L46 (-263.525, -65.0875) -> (-139.7, -65.0875)
  line L47 (-139.7, -65.0875) -> (139.7, -65.0875)
  line L48 (-263.525, -17.4625) -> (-263.525, 17.4625)
  line L49 (263.525, -17.4625) -> (263.525, 17.4625)
  circle C1 centre (0, 0) radius 50.8
  circle C2 centre (0, 0) radius 38.1
  circle C3 centre (26.9408, 26.9408) radius 7.1437
  circle C4 centre (-26.9408, 26.9408) radius 7.1437
  circle C5 centre (-26.9408, -26.9408) radius 7.1437
  circle C6 centre (26.9408, -26.9408) radius 7.1437
  circle C7 centre (0, 0) radius 50.8
  circle C8 centre (0, 0) radius 51.5937
  circle C9 centre (120.65, 0) radius 12.7
  point P1 (0, 0)
  point P3 (0, 0)
  point P4 (0, 0)
  point P5 (0, 38.1)
  point P6 (0, 0)
  point P7 (26.9408, 26.9408)
  point P8 (26.9408, 26.9408)
  point P15 (0, 65.0875)
  point P12 (0, 65.0875)
  point P17 (25.4, 44.9083)
  point P16 (0, 0)
  point P19 (0, 0)
  point P20 (120.65, 0)
  point P21 (120.65, 0)
  point P22 (120.65, 0)
  point P26 (120.65, 50.8)
  point P23 (120.65, 50.8)
  point P28 (263.525, 17.4625)
  point P30 (263.525, 17.4625)
  point P14 (12.7, 65.0875)
  point P33 (12.7, -65.0875)
  point P34 (25.4, -44.9083)
  point P18 (98.425, 36.4916)
  point P35 (98.425, -36.4916)
  point P39 (120.65, 0)
  point P40 (120.65, -50.8)
  point P24 (111.9187, 50.8)
  point P36 (111.9187, -50.8)
  point P25 (129.3812, 50.8)
  point P37 (129.3812, -50.8)
  point P27 (136.525, 32.1003)
  point P38 (136.525, -32.1003)
  point P41 (263.525, -17.4625)
  point P29 (263.525, 65.0875)
  point P43 (263.525, -65.0875)
  point P45 (263.525, -17.4625)
  point P31 (139.7, 65.0875)
  point P42 (139.7, -65.0875)
  point P32 (-139.7, 65.0875)
  point P44 (-139.7, -65.0875)
  point P46 (-12.7, 65.0875)
  point P47 (-25.4, 44.9083)
  point P48 (-98.425, 36.4916)
  point P49 (-111.9187, 50.8)
  point P50 (-129.3812, 50.8)
  point P51 (-136.525, 32.1003)
  point P52 (-263.525, 17.4625)
  point P61 (-263.525, 65.0875)
  point P62 (-263.525, 17.4625)
  point P60 (-139.7, 65.0875)
  point P63 (139.7, 65.0875)
  point P56 (-12.7, -65.0875)
  point P55 (-25.4, -44.9083)
  point P54 (-98.425, -36.4916)
  point P57 (-111.9187, -50.8)
  point P58 (-129.3812, -50.8)
  point P53 (-136.525, -32.1003)
  point P59 (-263.525, -17.4625)
  point P66 (-139.7, -65.0875)
  point P64 (-263.525, -65.0875)
  point P67 (139.7, -65.0875)
  point P65 (-263.525, -17.4625)
  point P13 (-12.7, 65.0875)
  coincident P1 P3
  coincident P3 P4
  coincident C2 P5
  vertical L1
  coincident P1 P6
  coincident C2 P7
  coincident P7 P8
  parallel L1 L3
  horizontal L4
  midpoint L4 P15
  coincident P12 P15
  coincident C8 P17
  coincident P16 P19
  horizontal L7
  coincident P20 P21
  coincident P21 P22
  perpendicular L7 L8
  horizontal L9
  midpoint L9 P26
  coincident P23 P26
  coincident P28 L13
  coincident P28 P30
  parallel L6 L12
  parallel L6 L14
  symmetric P14 L7 P33
  symmetric P17 L7 P34
  symmetric P18 L7 P35
  symmetric L7 P22 P39
  symmetric L7 P23 P40
  symmetric L7 P24 P36
  symmetric L7 P25 P37
  symmetric L7 P27 P38
  symmetric L7 P28 P41
  symmetric L7 P29 P43
  symmetric L7 P30 P45
  symmetric L7 P31 P42
  symmetric L7 P32 P44
  symmetric L1 P14 P46
  symmetric L1 P17 P47
  symmetric L1 P18 P48
  symmetric L1 P24 P49
  symmetric L1 P25 P50
  symmetric L1 P27 P51
  symmetric L1 P28 P52
  symmetric L1 P29 P61
  symmetric L1 P30 P62
  symmetric L1 P31 P60
  symmetric L1 P32 P63
  symmetric L1 P33 P56
  symmetric L1 P34 P55
  symmetric L1 P35 P54
  symmetric L1 P36 P57
  symmetric L1 P37 P58
  symmetric L1 P38 P53
  symmetric L1 P41 P59
  symmetric L1 P42 P66
  symmetric L1 P43 P64
  symmetric L1 P44 P67
  symmetric L1 P45 P65
  dimension "d142" diameter C2 = 76.2
  dimension "d143" angle L1 L2 = 45
  dimension "d144" diameter C3 = 14.2875 (= "( 9 / 16 ) * 1 in")
  dimension "d147" distance P1 P12 = 65.0875 (= "2 9/16")
  dimension "d148" distance P13 P14 = 25.4
  dimension "d149" distance L3 P17 = 25.4
  dimension "d151" distance P19 P20 = 120.65 (= "4 3/4")
  dimension "d152" diameter C9 = 25.4
  dimension "d153" distance P24 P25 = 17.4625 (= "( 11 / 16 ) * 1 in")
  dimension "d154" distance L7 L9 = 50.8
  dimension "d155" distance P18 L8 = 22.225 (= "( 7 / 8 ) * 1 in")
  dimension "d156" distance L8 P27 = 15.875 (= "( 5 / 8 ) * 1 in")
  dimension "d146" C-Pattern1-Angle = 360
extrude "Extrude6" cut sketch "Bottom Profile" profile of L5 L6 L9 L10 L11 L12 L13 L15 L16 L17 L18 L19 L20 L21 L24 L25 L26 L27 L44 L47 against normal blind 79.375
sketch "Web Profile 1" plane through (0, 0, 79.375) normal (0, 0, -1) x axis (1, 0, 0)
  line L1 (251.4089, -3.9687) -> (251.4089, -17.4625)
  line L2 (173.5531, -3.9688) -> (251.4089, -3.9687)
  line L3 (173.5531, 3.9688) -> (173.5531, -3.9688)
  line L4 (251.4089, 3.9688) -> (173.5531, 3.9688)
  line L5 (251.4089, 17.4625) -> (251.4089, 3.9688)
  line L6 (134.9375, 17.4625) -> (251.4089, 17.4625)
  line L7 (134.9375, -17.4625) -> (134.9375, 17.4625)
  line L8 (251.4089, -17.4625) -> (134.9375, -17.4625)
  line L9 (106.3625, 3.9688) -> (19.05, 3.9688)
  line L10 (106.3625, 17.4625) -> (106.3625, 3.9688)
  line L11 (19.05, 17.4625) -> (106.3625, 17.4625)
  line L12 (106.3625, -17.4625) -> (19.05, -17.4625)
  line L13 (106.3625, -3.9687) -> (106.3625, -17.4625)
  line L14 (19.05, -3.9688) -> (106.3625, -3.9687)
  line L15 (123.825, 38.1) -> (263.525, 17.4625)
  line L16 (0, 38.1) -> (123.825, 38.1)
  line L17 (0, 38.1) -> (0, 0)
  line L18 (251.4089, 18.859) -> (148.2214, 30.7522)
  line L19 (263.525, 0) -> (0, 0)
  line L20 (263.525, 17.4625) -> (263.525, 0)
  line L21 (19.05, 3.9688) -> (19.05, 17.4625)
  line L22 (19.05, -17.4625) -> (19.05, -3.9688)
  point P16 (263.525, 17.4625)
  point P17 (263.525, 17.4625)
  point P18 (123.825, 38.1)
  point P21 (120.65, 0)
  coincident P16 P17
  horizontal L16
  perpendicular L16 L17
  vertical L20
  dimension "d163" distance P18 P21 = 3.175 (= "( 1 / 8 ) * 1 in")
  dimension "d168" distance L16 L19 = 38.1 (= "1 1/2")
extrude "Extrude7" add sketch "Web Profile 1" profile of L3 L4 L5 L6 L7 L9 L10 L11 L15 L16 L17 L18 L19 L20 against normal blind 6.35 (magnitude of "( -1 / 4 ) * 1 in")
work_plane "WorkPlane2" RotateAngle 90
sketch "Web Profile 2" plane through (120.65, 0, 106.3625) normal (1, 0, 0) x axis (0, 1, 0)
  line L1 (-3.9688, 11.1125) -> (-3.9688, 78.5813)
  line L2 (-17.4625, 11.1125) -> (-3.9688, 11.1125)
  line L3 (-17.4625, 78.5813) -> (-17.4625, 11.1125)
  line L4 (-3.9688, 78.5813) -> (-17.4625, 78.5813)
  line L5 (-3.9688, -90.4875) -> (-3.9688, -26.9875)
  line L6 (-17.4625, -90.4875) -> (-3.9688, -90.4875)
  line L7 (-17.4625, -26.9875) -> (-17.4625, -90.4875)
  line L8 (-3.9688, -26.9875) -> (-17.4625, -26.9875)
  line L9 (-50.8, -103.1875) -> (-36.4916, -103.1875)
  line L10 (-50.8, -90.4875) -> (-50.8, -103.1875)
  line L11 (-36.4916, -90.4875) -> (-50.8, -90.4875)
  line L12 (-36.4916, -103.1875) -> (-36.4916, -90.4875)
  line L13 (-38.1, -20.6375) -> (-38.1, -26.9875)
  line L14 (-50.8, -90.4875) -> (-38.1, -26.9875)
  line L15 (-17.4625, 39.6875) -> (-38.1, -20.6375)
  line L16 (-17.4625, -26.9875) -> (-17.4625, 11.1125)
  line L17 (-17.4625, -90.4875) -> (-36.4916, -90.4875)
  point P14 (-38.1, -26.9875)
  point P16 (-38.1, -26.9875)
  point P12 (-50.8, -90.4875)
  point P17 (-50.8, -90.4875)
  point P15 (-38.1, -20.6375)
  point P18 (-38.1, -20.6375)
  point P19 (-17.4625, 39.6875)
  point P4 (-17.4625, 11.1125)
  point P20 (-17.4625, 11.1125)
  point P9 (-17.4625, -26.9875)
  point P21 (-17.4625, -26.9875)
  point P13 (-36.4916, -90.4875)
  point P22 (-36.4916, -90.4875)
  point P8 (-17.4625, -90.4875)
  point P23 (-17.4625, -90.4875)
  coincident P14 P16
  coincident P12 P17
  coincident P15 P18
  coincident L3 P19
  coincident P4 P20
  coincident P9 P21
  coincident P13 P22
  coincident P8 P23
  dimension "d169" distance P18 P19 = 60.325 (= "2 3/8")
extrude "Extrude8" add sketch "Web Profile 2" profile of L3 L7 L11 L13 L14 L15 L16 L17 distance -6.35 (= "( -1 / 4 ) * 1 in")
mirror "Mirror1" mirrorStitchTolerance 0.1016
sketch "Web Profile 3" plane through (0, 0, 0) normal (-1, 0, 0) x axis (0, -1, 0)
  line L1 (17.4625, 79.375) -> (17.4625, 85.725)
  line L2 (38.1, 79.375) -> (17.4625, 79.375)
  line L3 (38.1, 85.725) -> (38.1, 79.375)
  line L4 (17.4625, 85.725) -> (38.1, 85.725)
  line L5 (17.4625, 146.05) -> (17.4625, 85.725)
  line L6 (17.4625, 85.725) -> (17.4625, 146.05)
  line L7 (17.4625, 79.375) -> (17.4625, 85.725)
  line L8 (17.4625, 119.0625) -> (17.4625, 79.375)
  line L9 (17.4625, 119.0625) -> (17.4625, 109.5375)
  line L10 (17.4625, 98.425) -> (17.4625, 109.5375)
  line L11 (17.4625, 109.5375) -> (17.4625, 98.425)
  line L12 (17.4625, 117.475) -> (17.4625, 109.5375)
  line L13 (17.4625, 184.9438) -> (17.4625, 117.475)
  line L14 (17.4625, 174.625) -> (17.4625, 184.9438)
  line L15 (17.4625, 184.9438) -> (17.4625, 174.625)
  line L16 (17.4625, 117.475) -> (17.4625, 184.9438)
  line L17 (17.4625, 117.475) -> (17.4625, 109.5375)
  line L18 (17.4625, 98.425) -> (17.4625, 109.5375)
  line L19 (17.4625, 85.725) -> (17.4625, 98.425)
  line L20 (17.4625, 79.375) -> (17.4625, 85.725)
  line L21 (17.4625, 85.725) -> (17.4625, 79.375)
  line L22 (65.0875, 15.875) -> (38.1, 79.375)
  line L23 (19.05, 15.875) -> (65.0875, 15.875)
  line L24 (17.4625, 15.875) -> (17.4625, 79.375)
  line L25 (19.05, 15.875) -> (17.4625, 15.875)
  line L26 (17.4625, 15.875) -> (17.4625, 79.375)
  line L27 (17.4625, 79.375) -> (17.4625, 15.875)
  point P4 (38.1, 79.375)
  point P16 (38.1, 79.375)
  point P15 (65.0875, 15.875)
  point P17 (65.0875, 15.875)
  point P8 (17.4625, 79.375)
  point P20 (17.4625, 79.375)
  coincident P4 P16
  coincident P15 P17
  horizontal L23
  coincident P8 P20
  horizontal L25
  vertical L24
extrude "Extrude9" add sketch "Web Profile 3" profile of L2 L22 L23 L24 L25 distance 6.35 (= "( 1 / 4 ) * 1 in")
sketch "Web Profile 4" plane through (0, 0, 85.725) normal (0, 0, 1) x axis (-1, 0, 0)
  line L1 (-117.475, 17.4625) -> (-117.475, 38.1)
  line L2 (0, 17.4625) -> (-117.475, 17.4625)
  line L3 (0, 38.1) -> (0, 17.4625)
  line L4 (-117.475, 38.1) -> (0, 38.1)
  line L5 (-25.0866, 19.8438) -> (-35.4053, 19.8438)
  line L6 (-30.2459, 38.1) -> (-30.2459, 19.8438)
  arc A1 centre (-30.2459, 38.1) radius 11.9063 clockwise from (-18.3397, 38.1) to (-42.1522, 38.1)
  point P8 (-30.2459, 19.8438)
  point P9 (-30.2459, 19.8438)
  point P10 (-30.2459, 38.1)
  point P12 (-42.1522, 38.1)
  point P11 (-18.3397, 38.1)
  point P13 (-30.2459, 38.1)
  point P14 (-30.2459, 26.1937)
  midpoint L5 P8
  coincident P8 P9
  coincident L4 P10
  perpendicular L4 L6
  coincident L4 P12
  coincident L4 P11
  coincident P10 P13
  midpoint A1 P14
  dimension "d174" distance P8 P14 = 6.35 (= "( 1 / 4 ) * 1 in")
extrude "Extrude10" cut sketch "Web Profile 4" profile of L4 A1 against normal blind 6.35
mirror "Mirror2" mirrorStitchTolerance 0.1016
split "Split1"
remove_body "RemoveBody1"
fillet "Fillet1" radius 3.175 (= "( 1 / 8 ) * 1 in")
fillet "Fillet2" radius 25.4
fillet "Fillet26" radius 6.35 (= "( 1 / 4 ) * 1 in")
fillet "Fillet3" radius 31.75 (= "1 1/4")
chamfer "Chamfer3" distance 0.7257 distance 12.7
fillet "Fillet4" radius 11.1125 (= "( 7 / 16 ) * 1 in")
split "Split2"
remove_body "RemoveBody2"
fillet "Fillet10" radius 50.8
fillet "Fillet5" radius 1.5875 (= "( 1 / 16 ) * 1 in")
fillet "Fillet6" radius 3.175 (= "( 1 / 8 ) * 1 in")
fillet "Fillet8" radius 6.35 (= "( 1 / 4 ) * 1 in")
fillet "Fillet9" radius 3.175 (= "( 1 / 8 ) * 1 in")
fillet "Fillet11" radius 6.35 (= "( 1 / 4 ) * 1 in")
